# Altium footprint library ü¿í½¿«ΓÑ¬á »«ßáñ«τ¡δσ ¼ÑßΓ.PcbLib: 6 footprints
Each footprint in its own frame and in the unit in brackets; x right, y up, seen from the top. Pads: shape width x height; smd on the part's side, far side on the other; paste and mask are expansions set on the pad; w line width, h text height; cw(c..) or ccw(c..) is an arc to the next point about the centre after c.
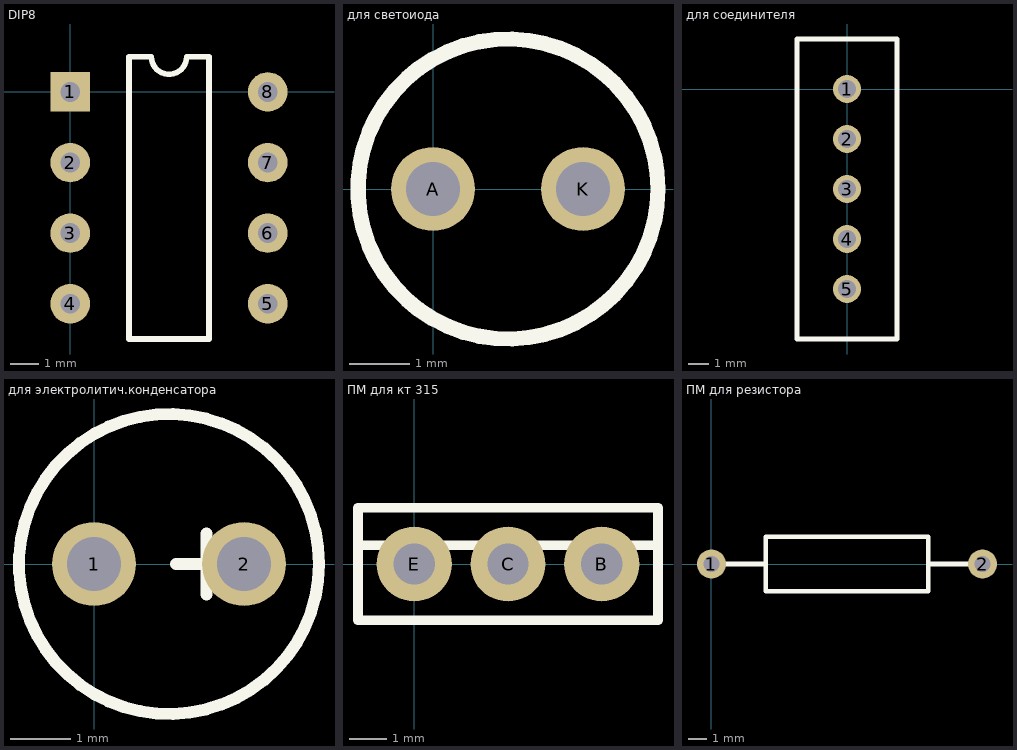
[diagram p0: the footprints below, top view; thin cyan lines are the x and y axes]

## DIP8 [mm]
pads (8):
  rect 1.4x1.4 hole 0.7: 1(0,0)
  round 1.4 hole 0.7: 2(0,-2.5) 3(0,-5) 4(0,-7.5) 5(7,-7.5) 6(7,-5) 7(7,-2.5) 8(7,0)
Top Overlay:
  lines w0.2: 2.085,-8.75 4.915,-8.75 4.915,1.25 4.125,1.25 cw(c3.5,1.25) 2.875,1.25 2.085,1.25 2.085,-8.75

## для светоиода [mm]
pads (2):
  round 1.4 hole 0.9: A(0,0) K(2.5,0)
Top Overlay:
  circle w0.254: c1.25,0 r2.5

## для соединителя [mm]
pads (5):
  round 1.4 hole 0.9: 1(0,0) 2(0,-2.5) 3(0,-5) 4(0,-7.5) 5(0,-10)
Top Overlay:
  lines w0.254: -2.5,-12.5 2.5,-12.5 2.5,2.5 -2.5,2.5 -2.5,-12.5

## для электролитич.конденсатора [mm]
pads (2):
  round 1.4 hole 0.9: 1(0,0) 2(2.5,0)
Top Overlay:
  circle w0.2: c1.25,0 r2.5
  lines w0.2: 1.367,0 2.383,0 ; 1.875,-0.508 1.875,0.508

## ПМ для кт 315 [mm]
pads (3):
  round 2 hole 1.1: B(5,0) C(2.5,0) E(0,0)
Top Overlay:
  lines w0.254: -1.5,0.5 6.5,0.5 ; -1.5,-1.5 -1.5,1.5 6.5,1.5 6.5,-1.5 -1.5,-1.5

## ПМ для резистора [mm]
pads (2):
  round 1.6 hole 0.9: 1(0,0) 2(15,0)
Top Overlay:
  lines w0.254: 0,0 3,0 ; 12,0 15,0 ; 3,-1.5 3,1.5 12,1.5 12,-1.5 3,-1.5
